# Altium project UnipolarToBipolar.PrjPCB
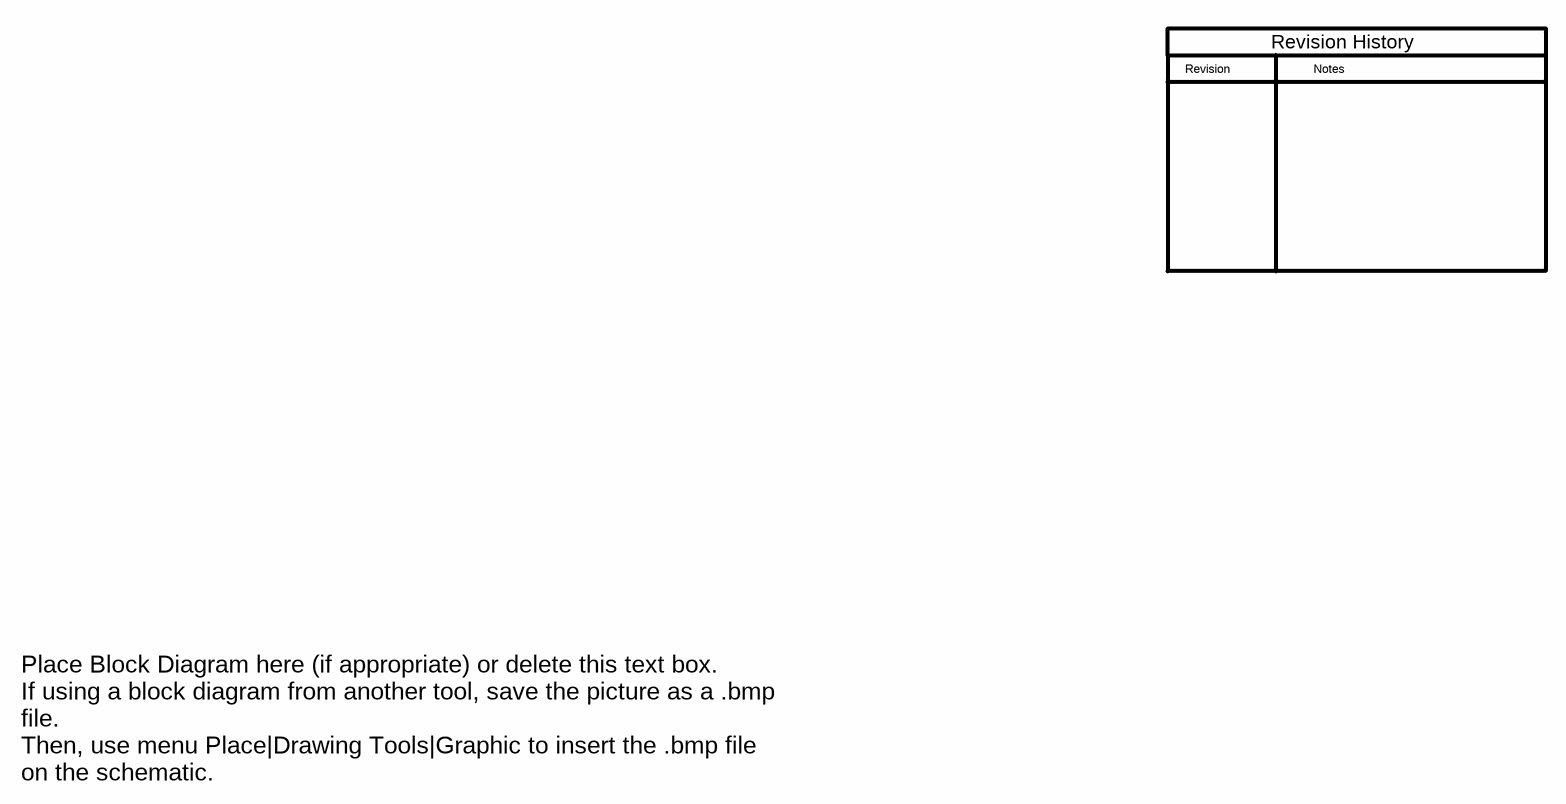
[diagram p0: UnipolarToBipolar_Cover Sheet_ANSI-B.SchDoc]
CopyrightYear: 2013; PCB_Layout: Kevin Duke; PCB_Rev: 1; PRJ_Customer: TI Precision Designs; PRJ_Engineer: Kevin Duke; PRJ_Number: 1; PRJ_Title: Unipolar to Bipolar; SCH_Rev: 1; TechSupport: http://www.ti.com/support
3 sheets, 43 parts. Net scope: global (net labels, ports and power ports of the same name join across sheets).
Board file: UnipolarToBipolar.PcbDoc
Sheets:
  UnipolarToBipolar_Cover Sheet_ANSI-B.SchDoc
  UnipolarToBipolar_ANSI-B.SchDoc
  Hardware_ANSI-B.SchDoc

## Sheet UnipolarToBipolar_Cover Sheet_ANSI-B.SchDoc
size 431 x 279 mm; Date: Not shown in title block; ApprovedBy: Not shown in title block; CheckedBy: Not shown in title block; Author: Not shown in title block; CompanyName: Not shown in title block; Engineer: Not shown in title block; Organization: Not shown in title block; Address1: Not shown in title block; Address2: Not shown in title block; Address3: Not shown in title block; Address4: Not shown in title block; DocumentNumber: 1; Revision: Use project parameter SCH_Rev; SheetNumber: 1; SheetTotal: 1; PageSetup: Record=PageOptions|CenterHorizontal=True|CenterVertical=True|PrintScale=1.00|XCorrection=1.00|YCorrection=1.00|PrintKind=0|BorderSize=5000000|LeftOffset=0|BottomOffset=0|Orientation=2|PaperLength=1000|PaperWidth=1000|Scale=100|PaperSource=15|PrintQuality=600|MediaType=1|DitherType=10|PaperKind=Letter|PrintScaleMode=1

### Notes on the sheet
- Revision
- Notes
- Revision History
- Place Block Diagram here (if appropriate) or delete this text box.
  If using a block diagram from another tool, save the picture as a .bmp file.
  Then, use menu Place|Drawing Tools|Graphic to insert the .bmp file on the schematic.

## Sheet UnipolarToBipolar_ANSI-B.SchDoc
size 431 x 279 mm; Date: Not shown in title block; ApprovedBy: Not shown in title block; CheckedBy: Not shown in title block; Author: Not shown in title block; CompanyName: Not shown in title block; Engineer: Not shown in title block; Organization: Not shown in title block; Address1: Not shown in title block; Address2: Not shown in title block; Address3: Not shown in title block; Address4: Not shown in title block; DocumentNumber: 1; Revision: Use project parameter SCH_Rev; SheetNumber: 1; SheetTotal: 1; PageSetup: Record=PageOptions|CenterHorizontal=True|CenterVertical=True|PrintScale=1.00|XCorrection=1.00|YCorrection=1.00|PrintKind=0|BorderSize=5000000|LeftOffset=0|BottomOffset=0|Orientation=2|PaperLength=1000|PaperWidth=1000|Scale=100|PaperSource=15|PrintQuality=600|MediaType=1|DitherType=10|PaperKind=Letter|PrintScaleMode=1
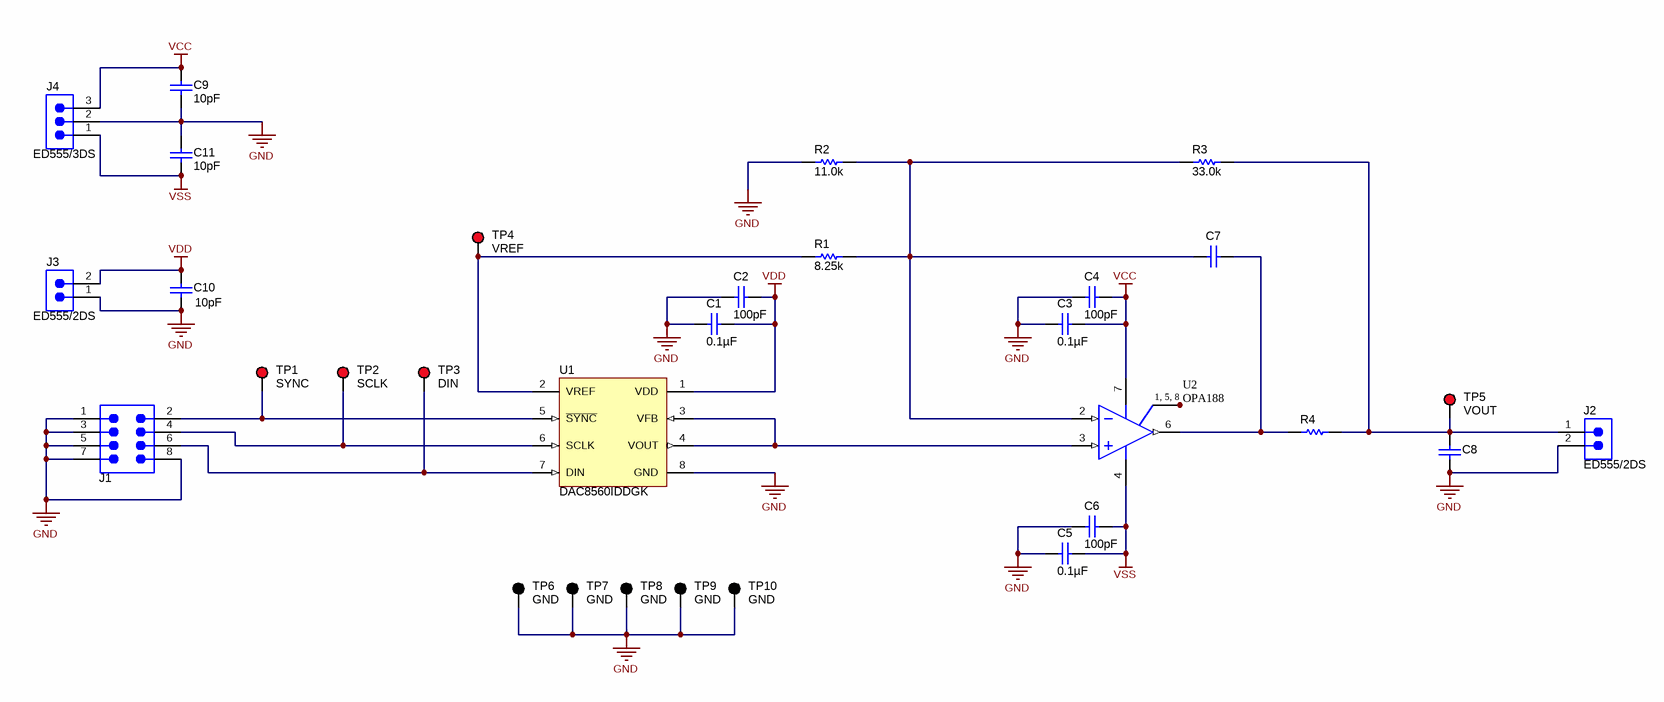
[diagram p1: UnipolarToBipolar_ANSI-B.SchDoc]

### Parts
C1  ValueDisplayed: 0.1µF  [0603]  (hidden comment: 06033C104JAT2A)
C2  ValueDisplayed: 100pF  [0603]  (hidden comment: 06035A101JAT2A)
C3  ValueDisplayed: 0.1µF  [0603]  (hidden comment: 06033C104JAT2A)
C4  ValueDisplayed: 100pF  [0603]  (hidden comment: 06035A101JAT2A)
C5  ValueDisplayed: 0.1µF  [0603]  (hidden comment: 06033C104JAT2A)
C6  ValueDisplayed: 100pF  [0603]  (hidden comment: 06035A101JAT2A)
C7  Used in BOM report  [0603]  (value not drawn)
C8  Used in BOM report  [0603]  (value not drawn)
C9  ValueDisplayed: 10pF  [0603]  (hidden comment: GRM1885C1H100JA01D)
C10  ValueDisplayed: 10pF  [0603]  (hidden comment: GRM1885C1H100JA01D)
C11  ValueDisplayed: 10pF  [0603]  (hidden comment: GRM1885C1H100JA01D)
J1  TSW-104-07-G-D  [TSW-104-07-G-D]  (value not drawn)
J2  ED555/2DS  [TERM_BLK_ED555-2DS]
J3  ED555/2DS  [TERM_BLK_ED555-2DS]
J4  ED555/3DS  [TERM_BLK_ED555-3DS]
R1  value 8.25k  [0603]  (hidden comment: RG1608P-8251-B-T5)
R2  value 11.0k  [0603]  (hidden comment: RG1608P-113-B-T5)
R3  value 33.0k  [0603]  (hidden comment: RG1608P-333-B-T5)
R4  Used in BOM report  [0603]  (value not drawn)
TP1  SYNC  [Keystone5000]
TP2  SCLK  [Keystone5000]
TP3  DIN  [Keystone5000]
TP4  VREF  [Keystone5000]
TP5  VOUT  [Keystone5000]
TP6  GND  [Keystone5001]
TP7  GND  [Keystone5001]
TP8  GND  [Keystone5001]
TP9  GND  [Keystone5001]
TP10  GND  [Keystone5001]
U1  DAC8560IDDGK  [DGK0008A_N]
U2  OPA188  [182H_N]

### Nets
GND: C1.2 C2.2 C3.2 C4.2 C5.2 C6.2 C8.2 C9.1 C10.2 C11.2 J1.1 J1.3 J1.5 J1.7 J1.8 J2.2 J3.1 J4.2 R2.1 TP6.1 TP7.1 TP8.1 TP9.1 TP10.1 U1.8(GND)
VCC: C3.1 C4.1 C9.2 J4.3 U2.7(V+)
VDD: C1.1 C2.1 C10.1 J3.2 U1.1(VDD)
VSS: C5.1 C6.1 C11.1 J4.1 U2.4(V-)
NetC7_1: C7.1 R4.1 U2.6(OUT)
NetC7_2: C7.2 R1.2 R2.2 R3.1 U2.2(IN-)
NetC8_1: C8.1 J2.1 R3.2 R4.2 TP5.1
NetJ1_2: J1.2 TP1.1 U1.5(~{SYNC})
NetJ1_4: J1.4 TP2.1 U1.6(SCLK)
NetJ1_6: J1.6 TP3.1 U1.7(DIN)
NetR1_1: R1.1 TP4.1 U1.2(VREF)
NetU1_3: U1.3(VFB) U1.4(VOUT) U2.3(IN+)
NetU2_1: U2.1(NC) U2.5(NC) U2.8(NC)

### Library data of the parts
C1 C3 C5 = 06033C104JAT2A: CAP, CERM, 0.1uF, 25V, +/-5%, X7R, 0603; Manufacturer: AVX; Polarized: N; CompType: Capacitor; U/M: EA; Cap_F: 0.0000001; Tolerance_%: 5; ESR_Ohm: 0.05; Value1: 0.05 ohm; VDC_V: 25; TaMin_C: -55; TaMax_C: 125
C2 C4 C6 = 06035A101JAT2A: CAP, CERM, 100pF, 50V, +/-5%, C0G/NP0, 0603; Manufacturer: AVX; Polarized: N; CompType: Capacitor; U/M: EA; Cap_F: 0.0000000001; Tolerance_%: 5; ESR_Ohm: 0.119; Value1: 0.119 ohm; VDC_V: 50; TaMin_C: -55; TaMax_C: 125
C7 C8 = Capacitor: CAP, CERM, xxxF, xxV, [TempCo], xx%, [PackageReference]; Polarized: N; U/M: EA
C9-C11 = GRM1885C1H100JA01D: CAP, CERM, 10pF, 50V, +/-5%, C0G/NP0, 0603; Manufacturer: MuRata; Polarized: N; CompType: Capacitor; U/M: EA; Cap_F: 0.00000000001; Tolerance_%: 5; Value1: Unknown; VDC_V: 50; TaMin_C: -55; TaMax_C: 125
J1 = TSW-104-07-G-D: Header, TH, 100mil, 4x2, Gold plated, 230 mil above insulator; Manufacturer: Samtec, Inc.; U/M: EA
J2 J3 = ED555/2DS: Terminal Block, 6A, 3.5mm Pitch, 2-Pos, TH; Manufacturer: On-Shore Technology, Inc.; SymbolCreator: a0412235; CompType: Connector; U/M: EA
J4 = ED555/3DS: Terminal Block, 6A, 3.5mm Pitch, 3-Pos, TH; Manufacturer: On-Shore Technology, Inc.; SymbolCreator: a0799628; CompType: Connector; U/M: EA
R1 = RG1608P-8251-B-T5: RES, 8.25k ohm, 0.1%, 0.1W, 0603; Manufacturer: Susumu Co Ltd; CompType: Resistor; Res_ohm: 8250; Value_Code: 8k25; Tolerance_%: 0.1; VDC_V: 75; TempCo: 25 ppm/C; EIA_Code: E192; U/M: EA
R2 = RG1608P-113-B-T5: RES, 11.0k ohm, 0.1%, 0.1W, 0603; Manufacturer: Susumu Co Ltd; CompType: Resistor; Res_ohm: 11000; Value_Code: 11k0; Tolerance_%: 0.1; VDC_V: 75; TempCo: 25 ppm/C; EIA_Code: E192; U/M: EA
R3 = RG1608P-333-B-T5: RES, 33.0k ohm, 0.1%, 0.1W, 0603; Manufacturer: Susumu Co Ltd; CompType: Resistor; Res_ohm: 33000; Value_Code: 33k0; Tolerance_%: 0.1; VDC_V: 75; TempCo: 25 ppm/C; U/M: EA
R4 = Resistor: RES, xxx ohm, x%, xW, [PackageReference]; U/M: EA
TP1-TP5 = 5000: Test Point, Miniature, Red, TH; Manufacturer: Keystone; CompType: Test Point Loop; U/M: EA
TP6-TP10 = 5001: Test Point, Miniature, Black, TH; Manufacturer: Keystone; CompType: Test Point Loop; U/M: EA
U1 = DAC8560IDDGK: 16-Bit, Ultra-Low Glitch, Voltage Output Digital-to-Analog Converter with 2.5V, 2ppm/°C Internal Reference, DGK0008A; Alternate Manufacturer: None; Manufacturer: Texas Instruments; SymbolCreator: a0411947; CompType: IC; U/M: EA
U2 = OPA650U: Wideband, Low-Power Voltage Feedback Operational Amplifier; Note: Pins 1, 5 and 8 are No internal Connection (NC) pins.

## Sheet Hardware_ANSI-B.SchDoc
size 431 x 279 mm; Date: Not shown in title block; ApprovedBy: Not shown in title block; CheckedBy: Not shown in title block; Author: Not shown in title block; CompanyName: Not shown in title block; Engineer: Not shown in title block; Organization: Not shown in title block; Address1: Not shown in title block; Address2: Not shown in title block; Address3: Not shown in title block; Address4: Not shown in title block; DocumentNumber: 1; Revision: Use project parameter SCH_Rev; SheetNumber: 1; SheetTotal: 1; PageSetup: Record=PageOptions|CenterHorizontal=True|CenterVertical=True|PrintScale=1.00|XCorrection=1.00|YCorrection=1.00|PrintKind=0|BorderSize=5000000|LeftOffset=0|BottomOffset=0|Orientation=2|PaperLength=1000|PaperWidth=1000|Scale=100|PaperSource=15|PrintQuality=600|MediaType=1|DitherType=10|PaperKind=Letter|PrintScaleMode=1
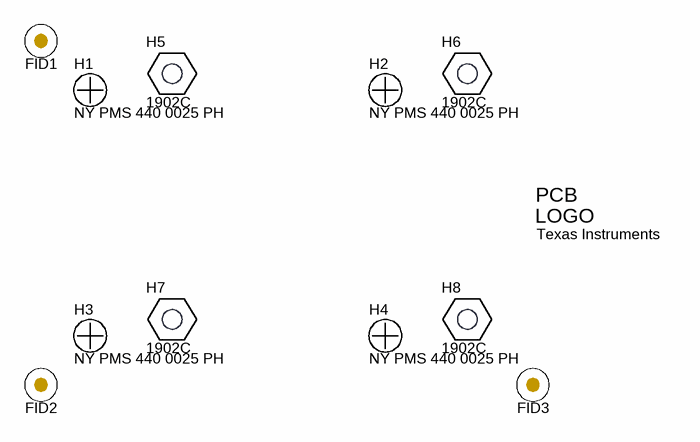
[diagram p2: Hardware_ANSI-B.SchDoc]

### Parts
FID1  Fiducial  [Fiducial10-20]  (value not drawn)
FID2  Fiducial  [Fiducial10-20]  (value not drawn)
FID3  Fiducial  [Fiducial10-20]  (value not drawn)
H1  NY PMS 440 0025 PH  [NY PMS 440 0025 PH]
H2  NY PMS 440 0025 PH  [NY PMS 440 0025 PH]
H3  NY PMS 440 0025 PH  [NY PMS 440 0025 PH]
H4  NY PMS 440 0025 PH  [NY PMS 440 0025 PH]
H5  1902C  [Keystone_1902C]
H6  1902C  [Keystone_1902C]
H7  1902C  [Keystone_1902C]
H8  1902C  [Keystone_1902C]
Logo1  Texas Instruments  [TI_Stacked_Overlay_Small]  (no BOM)

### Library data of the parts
FID1-FID3 = Fiducial: Fiducial mark.  There is nothing to buy or mount.; SymbolCreator: codlsc
H1-H4 = NY PMS 440 0025 PH: Machine Screw, Round, #4-40 x 1/4, Nylon, Philips panhead; Manufacturer: B&F Fastener Supply; CompType: Hardware; SymbolCreator: codlsc; U/M: EA
H5-H8 = 1902C: Standoff, Hex, 0.5"L #4-40 Nylon; Manufacturer: Keystone; CompType: Hardware
Logo1 = TI_Logo: Texas Instrument Corporate Signature; SymbolCreator: codlsc

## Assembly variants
001: all parts fitted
